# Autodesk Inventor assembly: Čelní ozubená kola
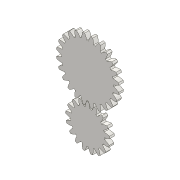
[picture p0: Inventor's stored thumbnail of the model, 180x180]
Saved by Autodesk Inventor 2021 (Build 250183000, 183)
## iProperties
ClientObjectVersion: 1
Created: 2024-11
Part Number: Čelní ozubená kola
Document SubType Name: Assembly
Designer: tatulinek
Categories: <?xml version="1.0" encoding="UTF-16"?> <MemberInstance><Categories><FamilyTemplate/><ParamToTemplateMap><ParamToTemplate><ParamToTemplate CategoryParameter="//
Author: tatulinek
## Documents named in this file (3)
- C:\Users\tatulinek\Documents\____Zviratka\Ozubena kola smazat3\Design Accelerator\Čelní ozubená kola1.iam
- C:\Users\tatulinek\Documents\____Zviratka\Ozubena kola smazat3\Design Accelerator\Čelní ozubené kolo11.ipt
- C:\Users\tatulinek\Documents\____Zviratka\Ozubena kola smazat3\Design Accelerator\Čelní ozubené kolo21.ipt
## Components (2 placed, 2 different names)
1. Čelní ozubené kolo1:1 — Rotace:1
2. Čelní ozubené kolo2:1 — Rotace:1
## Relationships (1: RelateRotation 1)
- Rotace:1 [RelateRotation]: Čelní ozubené kolo1:1 ↔ Čelní ozubené kolo2:1
